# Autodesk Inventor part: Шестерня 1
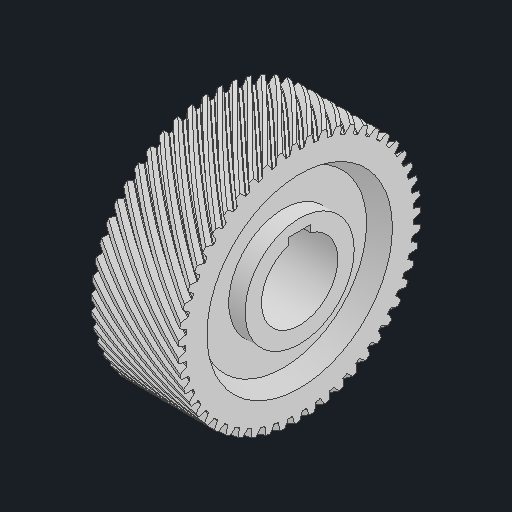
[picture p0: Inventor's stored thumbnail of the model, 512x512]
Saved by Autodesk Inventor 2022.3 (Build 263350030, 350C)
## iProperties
Created: 2020-09
Part Number: Шестерня 1
Material: Типовые
Document SubType Name: Modeling
Designer: Карташов
Density: 1 g/cm^3
Appearance: По умолчанию
Title: D:\мои документы\Ирина\_WorldSkills\2020_09 ФНЧ\Module A\GIVEN\Шестерня 1.stp
Author: Дом
Sending System: Autodesk Inventor 2021
Preprocessor: ST-DEVELOPER v18.1
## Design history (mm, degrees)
feature "Твердое тело2"
node "Твердое тело1"
